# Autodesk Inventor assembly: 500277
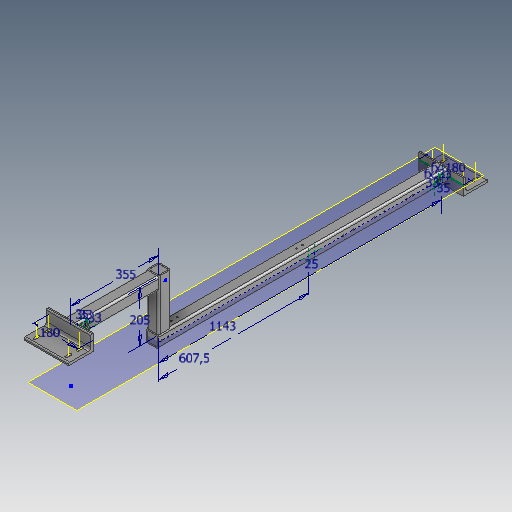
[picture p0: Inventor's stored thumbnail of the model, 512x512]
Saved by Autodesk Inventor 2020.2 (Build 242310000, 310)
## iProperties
Created: 1999-12
Part Number: 500277
Description: WMT-CP,TU,XX,MNT,PLOW,ADJUSTABLE
Document SubType Name: Assembly
Designer: sspink
Mass: 15989.1 g
Surface Area: 7123.65 cm^2
Volume: 2036.83 cm^3
Density: 7.85 g/cm^3
Control State: 0
Checked Out: False
Last Check In By: gpurviance
Last Check In Date: 2000-01-06
Master: False
Shininess: 0.0
Length Units: 11269
Angle Units: 11279
Time Units: 11290
Mass Units: 11283
Length Display Precision: 3
Angle Display Precision: 2
Compacted: True
_SolveAssemblyDoc: Frame Generator Solve Assembly
_Version: 15.0.0
Density: 0.0
Volumn: 0.0
Area: 0.0
PropertySet Name: Model Information
Dimensions: 270x1698x180 mm
Mass: 15,989 kg
DocNumber: 500277.iam
Folder: 01 - Themengebiete\Simplification\01 - Packaging machine\
VDS_Category: 3D Komponenten
Author: sspink
Revision Number: -
Title: 500277
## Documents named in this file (3)
- D:\07 - DEMODATEN\OTX 2019 - Dataset - UPDATE - Dez2019\Designs\07-Packing machine\500277.iam
- D:\07 - DEMODATEN\OTX 2019 - Dataset - UPDATE - Dez2019\Designs\07-Packing machine\Parts\ADSK-014172.ipt
- D:\07 - DEMODATEN\OTX 2019 - Dataset - UPDATE - Dez2019\Designs\07-Packing machine\500277\Frame\ADSK-014173.iam
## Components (2 placed, 2 different names)
1. ADSK-014172:1 — Fluchtend:13, Fluchtend:14, Fluchtend:15
2. ADSK-014173:1 [sub-assembly]
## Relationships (3: Flush 3)
- Fluchtend:13 [Flush]: ADSK-014172:1
- Fluchtend:14 [Flush]: ADSK-014172:1
- Fluchtend:15 [Flush]: ADSK-014172:1
